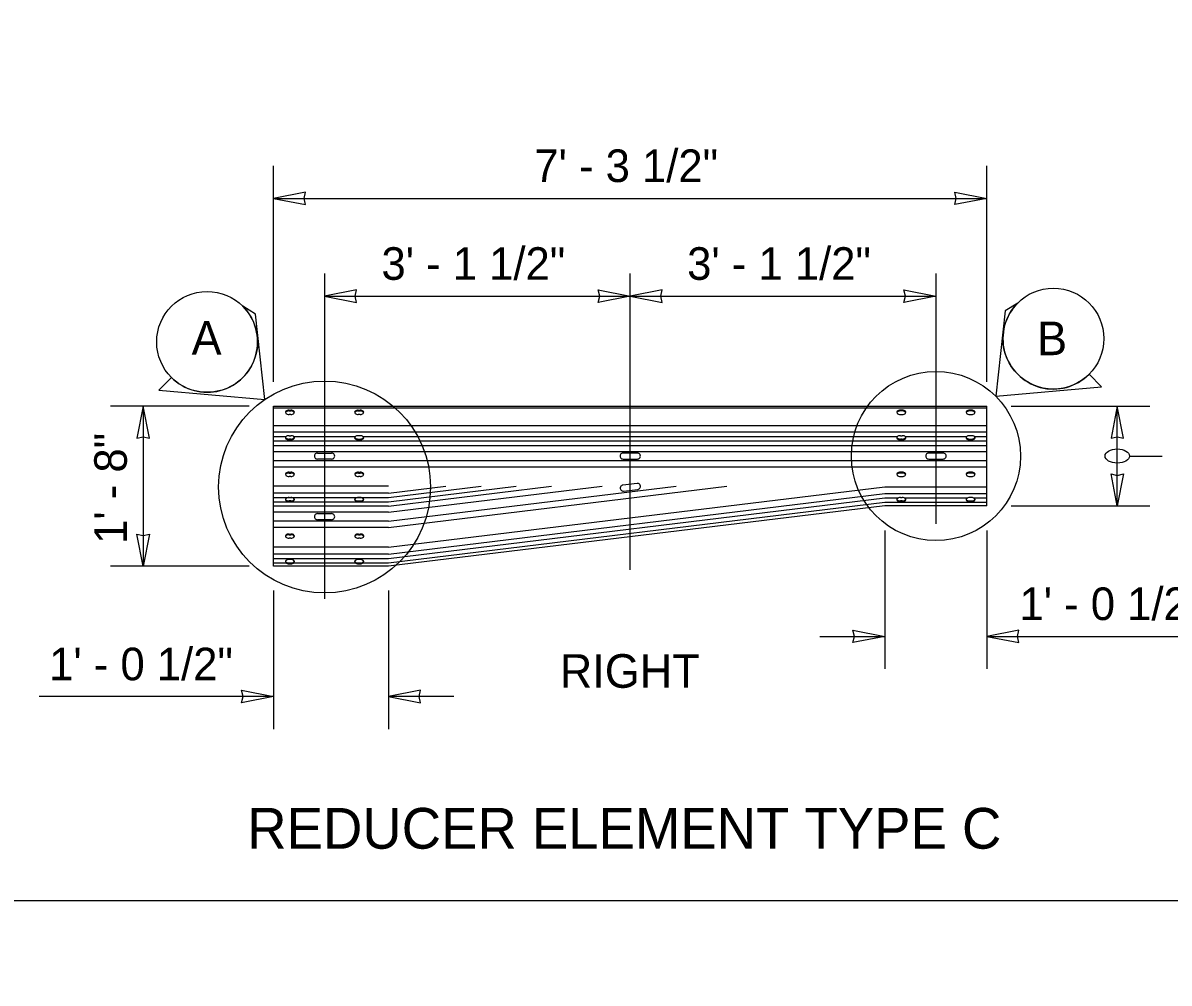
# Model space of a CAD drawing. Extents: x 34446 to 262144, y 33903 to 262144.
# Drawn here: x 101317 to 101879, y 99959 to 100430 of the extents above; entities that cross this region are included whole.
import ezdxf

# ---------------------------------------------------------------- set-up
doc = ezdxf.new("R2010")
doc.units = 0
for name, color, linetype in [('Level 1', 7, 'Continuous'), ('Level 12', 7, 'Continuous'), ('Level 15', 7, 'Continuous'), ('Level 20', 7, 'Continuous'), ('Level 3', 7, 'Continuous'), ('Level 5', 7, 'Continuous'), ('Level 9', 7, 'Continuous')]:
    doc.layers.add(name, color=color, linetype=linetype)

msp = doc.modelspace()

# ---------------------------------------------------------------- linework, layer by layer
at = {"layer": 'Level 1'}
msp.add_lwpolyline([(99862, 99999.5), (103151, 99999.5), (103151, 102075.5), (99862, 102075.5)], close=True, dxfattribs=at)
at = {"layer": 'Level 12'}
for p, q in [((101440.09, 100163.62), (101440.09, 100242.19)), ((101440.09, 100242.19), (101790.09, 100242.19)), ((101790.09, 100193.19), (101790.09, 100242.19)), ((101740.09, 100193.19), (101496.48, 100163.62)), ((101790.09, 100193.19), (101740.09, 100193.19)), ((101496.48, 100163.62), (101440.09, 100163.62))]:
    msp.add_line(p, q, dxfattribs=at)
for points in [[(101461.59, 100219.18), (101468.59, 100219.18)], [(101618.59, 100219.18), (101611.59, 100219.18)], [(101768.59, 100219.18), (101761.59, 100219.18)], [(101468.59, 100216.2), (101461.59, 100216.2)], [(101611.59, 100216.2), (101618.59, 100216.2)], [(101761.59, 100216.2), (101768.59, 100216.2)], [(101618.42, 100204.28), (101611.48, 100203.43)], [(101611.84, 100200.47), (101618.79, 100201.32)], [(101461.59, 100189.42), (101468.59, 100189.42)], [(101468.59, 100186.43), (101461.59, 100186.43)]]:
    msp.add_lwpolyline(points, dxfattribs=at)
for centre, major_axis, start_param, end_param in [((101461.59, 100217.69), (-1.5, 0), 4.712389, 7.853982), ((101468.59, 100217.69), (-1.5, 0), 1.570796, 4.712389), ((101611.59, 100217.69), (1.5, 0), 1.570796, 4.712389), ((101618.59, 100217.69), (1.5, 0), 4.712389, 7.853982), ((101761.59, 100217.69), (1.5, 0), 1.570796, 4.712389), ((101768.59, 100217.69), (1.5, 0), 4.712389, 7.853982), ((101611.66, 100201.95), (1.5, 0), 1.692581, 4.834174), ((101618.61, 100202.8), (1.5, 0), 4.834174, 7.975767), ((101461.59, 100187.93), (-1.5, 0), 4.712389, 7.853982), ((101468.59, 100187.93), (-1.5, 0), 1.570796, 4.712389)]:
    msp.add_ellipse(centre, major_axis=major_axis, ratio=0.994924, start_param=start_param, end_param=end_param, dxfattribs=at)
at = {"layer": 'Level 15'}
for p, q in [((101440.09, 100254.19), (101440.09, 100360.19)), ((101790.09, 100254.19), (101790.09, 100360.19)), ((101440.09, 100344.19), (101790.09, 100344.19)), ((101465.09, 100307.25), (101465.09, 100147.62)), ((101615.09, 100161.9), (101615.09, 100307.25)), ((101765.09, 100307.25), (101765.09, 100184.37)), ((101465.09, 100296.19), (101615.09, 100296.19)), ((101615.09, 100296.19), (101765.09, 100296.19)), ((101802.09, 100242.19), (101870.09, 100242.19)), ((101854.09, 100193.19), (101854.09, 100242.19)), ((101860.09, 100217.69), (101876.09, 100217.69)), ((101802.09, 100193.19), (101870.09, 100193.19)), ((101708.09, 100129.19), (101740.09, 100129.19)), ((101790.09, 100129.19), (101903.55, 100129.19))]:
    msp.add_line(p, q, dxfattribs=at)
for points in [[(101440.09, 100344.19), (101455.82, 100341.11), (101455.09, 100344.19), (101455.82, 100347.27)], [(101790.09, 100344.19), (101774.37, 100341.11), (101775.1, 100344.19), (101774.37, 100347.27)], [(101465.09, 100296.19), (101480.82, 100293.11), (101480.09, 100296.19), (101480.82, 100299.27)], [(101615.09, 100296.19), (101599.37, 100293.11), (101600.1, 100296.19), (101599.37, 100299.27)], [(101615.09, 100296.19), (101630.82, 100293.11), (101630.09, 100296.19), (101630.82, 100299.27)], [(101765.09, 100296.19), (101749.37, 100293.11), (101750.1, 100296.19), (101749.37, 100299.27)], [(101854.09, 100242.19), (101851.01, 100226.46), (101854.09, 100227.19), (101857.18, 100226.46)], [(101854.09, 100193.19), (101851.01, 100208.91), (101854.09, 100208.19), (101857.18, 100208.91)], [(101740.09, 100129.19), (101724.37, 100126.11), (101725.1, 100129.19), (101724.37, 100132.27)], [(101790.09, 100129.19), (101805.82, 100126.11), (101805.09, 100129.19), (101805.82, 100132.27)]]:
    msp.add_lwpolyline(points, close=True, dxfattribs=at)
for centre, radius in [((101765.09, 100217.69), 41.5), ((101465.11, 100202.52), 52)]:
    msp.add_circle(centre, radius, dxfattribs=at)
msp.add_ellipse((101854.09, 100217.69), major_axis=(-6, 0), ratio=0.57735, dxfattribs=at)
at = {"layer": 'Level 20'}
for p, q in [((101740.09, 100181.19), (101740.09, 100113.19)), ((101790.09, 100181.19), (101790.09, 100113.19)), ((101440.09, 100151.62), (101440.09, 100083.62)), ((101496.48, 100151.62), (101496.48, 100083.62))]:
    msp.add_line(p, q, dxfattribs=at)
at = {"layer": 'Level 3'}
for p, q in [((101428.09, 100242.19), (101360.09, 100242.19)), ((101376.09, 100242.19), (101376.09, 100163.62)), ((101428.09, 100163.62), (101360.09, 100163.62)), ((101440.09, 100099.62), (101325.02, 100099.62)), ((101528.48, 100099.62), (101496.48, 100099.62))]:
    msp.add_line(p, q, dxfattribs=at)
for points in [[(101376.09, 100242.19), (101373.01, 100226.46), (101376.09, 100227.19), (101379.18, 100226.46)], [(101376.09, 100163.62), (101373.01, 100179.34), (101376.09, 100178.62), (101379.18, 100179.34)], [(101440.09, 100099.62), (101424.37, 100096.54), (101425.1, 100099.62), (101424.37, 100102.7)], [(101496.48, 100099.62), (101512.2, 100096.54), (101511.48, 100099.62), (101512.2, 100102.7)]]:
    msp.add_lwpolyline(points, close=True, dxfattribs=at)
at = {"layer": 'Level 5'}
msp.add_spline([(100965.33, 100576.22), (100979.73, 100581.07), (100976.65, 100587.06), (100980.64, 100590.15), (100978.82, 100594.87), (100978.82, 100594.87), (100972.35, 100605.26)], degree=3, dxfattribs=at)
at = {"layer": 'Level 9'}
for p, q in [((101805.21, 100292.81), (101799.03, 100288.99)), ((101431.18, 100287.41), (101425, 100291.23)), ((101435.77, 100245.45), (101431.18, 100287.41)), ((101799.03, 100288.99), (101794.44, 100247.03)), ((101846.4, 100251.62), (101840.21, 100257.81)), ((101390, 100256.23), (101383.81, 100250.04)), ((101383.81, 100250.04), (101435.77, 100245.45)), ((101794.44, 100247.03), (101846.4, 100251.62)), ((101440.09, 100241.31), (101790.09, 100241.31)), ((101440.09, 100241.31), (101790.09, 100241.31)), ((101447.66, 100240.22), (101448.53, 100240.22)), ((101447.66, 100239.82), (101448.53, 100239.82)), ((101448.53, 100238.1), (101447.66, 100238.1)), ((101481.66, 100240.22), (101482.53, 100240.22)), ((101481.66, 100239.82), (101482.53, 100239.82)), ((101482.53, 100238.1), (101481.66, 100238.1)), ((101748.53, 100240.22), (101747.66, 100240.22)), ((101748.53, 100239.82), (101747.66, 100239.82)), ((101747.66, 100238.1), (101748.53, 100238.1)), ((101782.53, 100240.22), (101781.66, 100240.22)), ((101782.53, 100239.82), (101781.66, 100239.82)), ((101781.66, 100238.1), (101782.53, 100238.1)), ((101440.09, 100232.76), (101790.09, 100232.76)), ((101440.09, 100229.53), (101790.09, 100229.53)), ((101440.09, 100227.34), (101446.31, 100227.34)), ((101440.09, 100225.14), (101790.09, 100225.14)), ((101447.66, 100227.68), (101448.53, 100227.68)), ((101448.53, 100226.04), (101447.66, 100226.04)), ((101448.53, 100225.63), (101447.66, 100225.63)), ((101449.88, 100227.34), (101480.31, 100227.34)), ((101482.53, 100227.68), (101481.66, 100227.68)), ((101481.66, 100226.04), (101482.53, 100226.04)), ((101481.66, 100225.63), (101482.53, 100225.63)), ((101483.88, 100227.34), (101746.31, 100227.34)), ((101747.66, 100227.68), (101748.53, 100227.68)), ((101748.53, 100226.04), (101747.66, 100226.04)), ((101748.53, 100225.63), (101747.66, 100225.63)), ((101749.88, 100227.34), (101780.31, 100227.34)), ((101782.53, 100227.68), (101781.66, 100227.68)), ((101781.66, 100226.04), (101782.53, 100226.04)), ((101781.66, 100225.63), (101782.53, 100225.63)), ((101783.88, 100227.34), (101790.09, 100227.34)), ((101440.09, 100222.94), (101790.09, 100222.94)), ((101440.09, 100219.91), (101790.09, 100219.91)), ((101440.09, 100215.46), (101790.09, 100215.46)), ((101440.09, 100212.43), (101790.09, 100212.43)), ((101447.66, 100209.75), (101448.53, 100209.75)), ((101447.66, 100209.34), (101448.53, 100209.34)), ((101448.53, 100207.7), (101447.66, 100207.7)), ((101481.69, 100209.75), (101482.56, 100209.75)), ((101481.69, 100209.34), (101482.56, 100209.34)), ((101482.56, 100207.7), (101481.69, 100207.7)), ((101748.5, 100209.75), (101747.63, 100209.75)), ((101748.5, 100209.34), (101747.63, 100209.34)), ((101747.63, 100207.7), (101748.5, 100207.7)), ((101782.53, 100209.75), (101781.66, 100209.75)), ((101782.53, 100209.34), (101781.66, 100209.34)), ((101781.66, 100207.7), (101782.53, 100207.7)), ((101496.48, 100202.9), (101440.09, 100202.9)), ((101496.48, 100182.69), (101662.52, 100202.9)), ((101496.48, 100185.72), (101637.62, 100202.9)), ((101496.48, 100190.14), (101601.33, 100202.9)), ((101496.48, 100193.17), (101576.44, 100202.9)), ((101496.48, 100195.27), (101559.19, 100202.9)), ((101496.48, 100197.37), (101541.94, 100202.9)), ((101496.48, 100199.47), (101524.69, 100202.9)), ((101496.48, 100172.95), (101740.09, 100202.61)), ((101740.09, 100202.61), (101790.09, 100202.61)), ((101740.09, 100202.61), (101790.09, 100202.61)), ((101496.48, 100199.47), (101440.09, 100199.47)), ((101440.09, 100197.37), (101496.48, 100197.37)), ((101447.66, 100197.35), (101448.53, 100197.35)), ((101482.53, 100197.35), (101481.66, 100197.35)), ((101496.48, 100169.51), (101740.09, 100199.38)), ((101496.48, 100167.41), (101740.09, 100197.19)), ((101740.09, 100199.38), (101790.09, 100199.38)), ((101740.09, 100199.38), (101790.09, 100199.38)), ((101740.09, 100197.19), (101746.68, 100197.19)), ((101747.66, 100197.35), (101748.53, 100197.35)), ((101749.51, 100197.19), (101780.68, 100197.19)), ((101782.53, 100197.35), (101781.66, 100197.35)), ((101783.51, 100197.19), (101790.09, 100197.19)), ((101440.09, 100195.27), (101496.48, 100195.27)), ((101496.48, 100193.17), (101440.09, 100193.17)), ((101496.48, 100190.14), (101440.09, 100190.14)), ((101448.53, 100195.71), (101447.66, 100195.71)), ((101448.53, 100195.3), (101447.66, 100195.3)), ((101481.66, 100195.71), (101482.53, 100195.71)), ((101481.66, 100195.3), (101482.53, 100195.3)), ((101496.48, 100165.31), (101740.09, 100194.99)), ((101740.09, 100194.99), (101790.09, 100194.99)), ((101740.09, 100194.99), (101790.09, 100194.99)), ((101748.53, 100195.71), (101747.66, 100195.71)), ((101748.53, 100195.3), (101747.66, 100195.3)), ((101781.66, 100195.71), (101782.53, 100195.71)), ((101781.66, 100195.3), (101782.53, 100195.3)), ((101496.48, 100185.72), (101440.09, 100185.72)), ((101496.48, 100182.69), (101440.09, 100182.69)), ((101447.66, 100179.42), (101448.53, 100179.42)), ((101447.66, 100179.01), (101448.53, 100179.01)), ((101481.72, 100179.42), (101482.59, 100179.42)), ((101481.72, 100179.01), (101482.59, 100179.01)), ((101448.53, 100177.37), (101447.66, 100177.37)), ((101482.59, 100177.37), (101481.72, 100177.37)), ((101496.48, 100172.95), (101440.09, 100172.95)), ((101496.48, 100169.51), (101440.09, 100169.51)), ((101440.09, 100167.41), (101496.48, 100167.41)), ((101440.09, 100165.31), (101446.11, 100165.31)), ((101448.53, 100166.92), (101447.66, 100166.92)), ((101447.66, 100165.2), (101448.53, 100165.2)), ((101447.66, 100164.8), (101448.53, 100164.8)), ((101450.07, 100165.31), (101480.11, 100165.31)), ((101482.53, 100166.92), (101481.66, 100166.92)), ((101481.66, 100165.2), (101482.53, 100165.2)), ((101481.66, 100164.8), (101482.53, 100164.8)), ((101484.07, 100165.31), (101496.48, 100165.31))]:
    msp.add_line(p, q, dxfattribs=at)
for centre in [(101407.5, 100273.73), (101822.71, 100275.31)]:
    msp.add_circle(centre, 24.75, dxfattribs=at)
for centre, start, end in [((101822.71, 100275.31), 134.9978, 315.0022), ((101407.5, 100273.73), 224.9978, 45.0022)]:
    msp.add_arc(centre, 24.75, start, end, dxfattribs=at)
for centre, major_axis, ratio, start_param, end_param in [((101447.66, 100239.16), (-1.8, 0), 0.587551, 4.712389, 7.853982), ((101447.66, 100238.76), (-1.8, 0), 0.587551, 4.712389, 6.092062), ((101448.53, 100239.16), (-1.8, 0), 0.587551, 1.570796, 4.712389), ((101448.53, 100238.76), (-1.8, 0), 0.587551, 3.332716, 4.712389), ((101481.66, 100239.16), (-1.8, 0), 0.587551, 4.712389, 7.853982), ((101481.66, 100238.76), (-1.8, 0), 0.587551, 4.712389, 6.092062), ((101482.53, 100239.16), (-1.8, 0), 0.587551, 1.570796, 4.712389), ((101482.53, 100238.76), (-1.8, 0), 0.587551, 3.332716, 4.712389), ((101747.66, 100239.16), (-1.8, 0), 0.587551, 4.712389, 7.853982), ((101747.66, 100238.76), (-1.8, 0), 0.587551, 4.712389, 6.092062), ((101748.53, 100239.16), (-1.8, 0), 0.587551, 1.570796, 4.712389), ((101748.53, 100238.76), (-1.8, 0), 0.587551, 3.332716, 4.712389), ((101781.66, 100239.16), (-1.8, 0), 0.587551, 4.712389, 7.853982), ((101781.66, 100238.76), (-1.8, 0), 0.587551, 4.712389, 6.092062), ((101782.53, 100239.16), (-1.8, 0), 0.587551, 1.570796, 4.712389), ((101782.53, 100238.76), (-1.8, 0), 0.587551, 3.332716, 4.712389), ((101447.66, 100226.66), (-1.8, 0), 0.568261, 4.712389, 7.853982), ((101447.66, 100227.06), (-1.8, 0), 0.568261, 0.197752, 1.570796), ((101448.53, 100226.66), (-1.8, 0), 0.568261, 1.570796, 4.712389), ((101448.53, 100227.06), (-1.8, 0), 0.568261, 1.570796, 2.943841), ((101481.66, 100226.66), (-1.8, 0), 0.568261, 4.712389, 7.853982), ((101481.66, 100227.06), (-1.8, 0), 0.568261, 0.197752, 1.570796), ((101482.53, 100226.66), (-1.8, 0), 0.568261, 1.570796, 4.712389), ((101482.53, 100227.06), (-1.8, 0), 0.568261, 1.570796, 2.943841), ((101747.66, 100226.66), (-1.8, 0), 0.568261, 4.712389, 7.853982), ((101747.66, 100227.06), (-1.8, 0), 0.568261, 0.197752, 1.570796), ((101748.53, 100226.66), (-1.8, 0), 0.568261, 1.570796, 4.712389), ((101748.53, 100227.06), (-1.8, 0), 0.568261, 1.570796, 2.943841), ((101781.66, 100226.66), (-1.8, 0), 0.568261, 4.712389, 7.853982), ((101781.66, 100227.06), (-1.8, 0), 0.568261, 0.197752, 1.570796), ((101782.53, 100226.66), (-1.8, 0), 0.568261, 1.570796, 4.712389), ((101782.53, 100227.06), (-1.8, 0), 0.568261, 1.570796, 2.943841), ((101447.66, 100208.72), (1.8, 0), 0.568261, 1.570796, 4.712389), ((101447.66, 100208.32), (1.8, 0), 0.568261, 1.570796, 2.943841), ((101448.53, 100208.72), (1.8, 0), 0.568261, 4.712389, 7.853982), ((101448.53, 100208.32), (1.8, 0), 0.568261, 0.197752, 1.570796), ((101481.69, 100208.72), (1.8, 0), 0.568261, 1.570796, 4.712389), ((101481.69, 100208.32), (1.8, 0), 0.568261, 1.570796, 2.943841), ((101482.56, 100208.72), (1.8, 0), 0.568261, 4.712389, 7.853982), ((101482.56, 100208.32), (1.8, 0), 0.568261, 0.197752, 1.570796), ((101747.63, 100208.72), (1.8, 0), 0.568261, 1.570796, 4.712389), ((101747.63, 100208.32), (1.8, 0), 0.568261, 1.570796, 2.943841), ((101748.5, 100208.72), (1.8, 0), 0.568261, 4.712389, 7.853982), ((101748.5, 100208.32), (1.8, 0), 0.568261, 0.197752, 1.570796), ((101781.66, 100208.72), (1.8, 0), 0.568261, 1.570796, 4.712389), ((101781.66, 100208.32), (1.8, 0), 0.568261, 1.570796, 2.943841), ((101782.53, 100208.72), (1.8, 0), 0.568261, 4.712389, 7.853982), ((101782.53, 100208.32), (1.8, 0), 0.568261, 0.197752, 1.570796), ((101447.66, 100196.33), (-1.8, 0), 0.568261, 4.712389, 7.853982), ((101447.66, 100196.73), (-1.8, 0), 0.568261, 0.197752, 1.570796), ((101448.53, 100196.33), (-1.8, 0), 0.568261, 1.570796, 4.712389), ((101448.53, 100196.73), (-1.8, 0), 0.568261, 1.570796, 2.943841), ((101481.66, 100196.33), (-1.8, 0), 0.568261, 4.712389, 7.853982), ((101481.66, 100196.73), (-1.8, 0), 0.568261, 0.197752, 1.570796), ((101482.53, 100196.33), (-1.8, 0), 0.568261, 1.570796, 4.712389), ((101482.53, 100196.73), (-1.8, 0), 0.568261, 1.570796, 2.943841), ((101747.66, 100196.33), (-1.8, 0), 0.568261, 4.712389, 7.853982), ((101747.66, 100196.73), (-1.8, 0), 0.568261, 0.197752, 1.570796), ((101748.53, 100196.33), (-1.8, 0), 0.568261, 1.570796, 4.712389), ((101748.53, 100196.73), (-1.8, 0), 0.568261, 1.570796, 2.943841), ((101781.66, 100196.33), (-1.8, 0), 0.568261, 4.712389, 7.853982), ((101781.66, 100196.73), (-1.8, 0), 0.568261, 0.197752, 1.570796), ((101782.53, 100196.33), (-1.8, 0), 0.568261, 1.570796, 4.712389), ((101782.53, 100196.73), (-1.8, 0), 0.568261, 1.570796, 2.943841), ((101447.66, 100178.39), (1.8, 0), 0.568261, 1.570796, 4.712389), ((101447.66, 100177.99), (1.8, 0), 0.568261, 1.570796, 2.943841), ((101448.53, 100178.39), (1.8, 0), 0.568261, 4.712389, 7.853982), ((101448.53, 100177.99), (1.8, 0), 0.568261, 0.197752, 1.570796), ((101481.72, 100178.39), (1.8, 0), 0.568261, 1.570796, 4.712389), ((101481.72, 100177.99), (1.8, 0), 0.568261, 1.570796, 2.943841), ((101482.59, 100178.39), (1.8, 0), 0.568261, 4.712389, 7.853982), ((101482.59, 100177.99), (1.8, 0), 0.568261, 0.197752, 1.570796), ((101447.66, 100165.86), (1.8, 0), 0.587551, 1.570796, 4.712389), ((101447.66, 100166.26), (1.8, 0), 0.587551, 3.332716, 4.712389), ((101448.53, 100165.86), (1.8, 0), 0.587551, 4.712389, 7.853982), ((101448.53, 100166.26), (1.8, 0), 0.587551, 4.712389, 6.092062), ((101481.66, 100165.86), (1.8, 0), 0.587551, 1.570796, 4.712389), ((101481.66, 100166.26), (1.8, 0), 0.587551, 3.332716, 4.712389), ((101482.53, 100165.86), (1.8, 0), 0.587551, 4.712389, 7.853982), ((101482.53, 100166.26), (1.8, 0), 0.587551, 4.712389, 6.092062)]:
    msp.add_ellipse(centre, major_axis=major_axis, ratio=ratio, start_param=start_param, end_param=end_param, dxfattribs=at)

# ---------------------------------------------------------------- texts
at = {"layer": 'Level 20'}
for s, height, p in [('7\' - 3 1/2"', 16, (101568.03, 100352.19)), ('3\' - 1 1/2"', 16, (101493.03, 100304.19)), ('3\' - 1 1/2"', 16, (101643.03, 100304.19)), ('A', 16.5, (101399.87, 100267.44)), ('B', 16.5, (101814.75, 100267.2)), ('RIGHT', 16.5, (101580.54, 100103.94)), ('REDUCER ELEMENT TYPE C', 20, (101427.17, 100024.96))]:
    msp.add_text(s, height=height, dxfattribs=at).set_placement(p)
for s, rotation, p in [('1\' - 8"', 90, (101368.09, 100174.57)), ('1\' - 0 1/2"', 360, (101806.09, 100137.19)), ('1\' - 0 1/2"', 360, (101329.97, 100107.62))]:
    msp.add_text(s, height=16, rotation=rotation, dxfattribs=at).set_placement(p)

doc.saveas('drawing.dxf')
